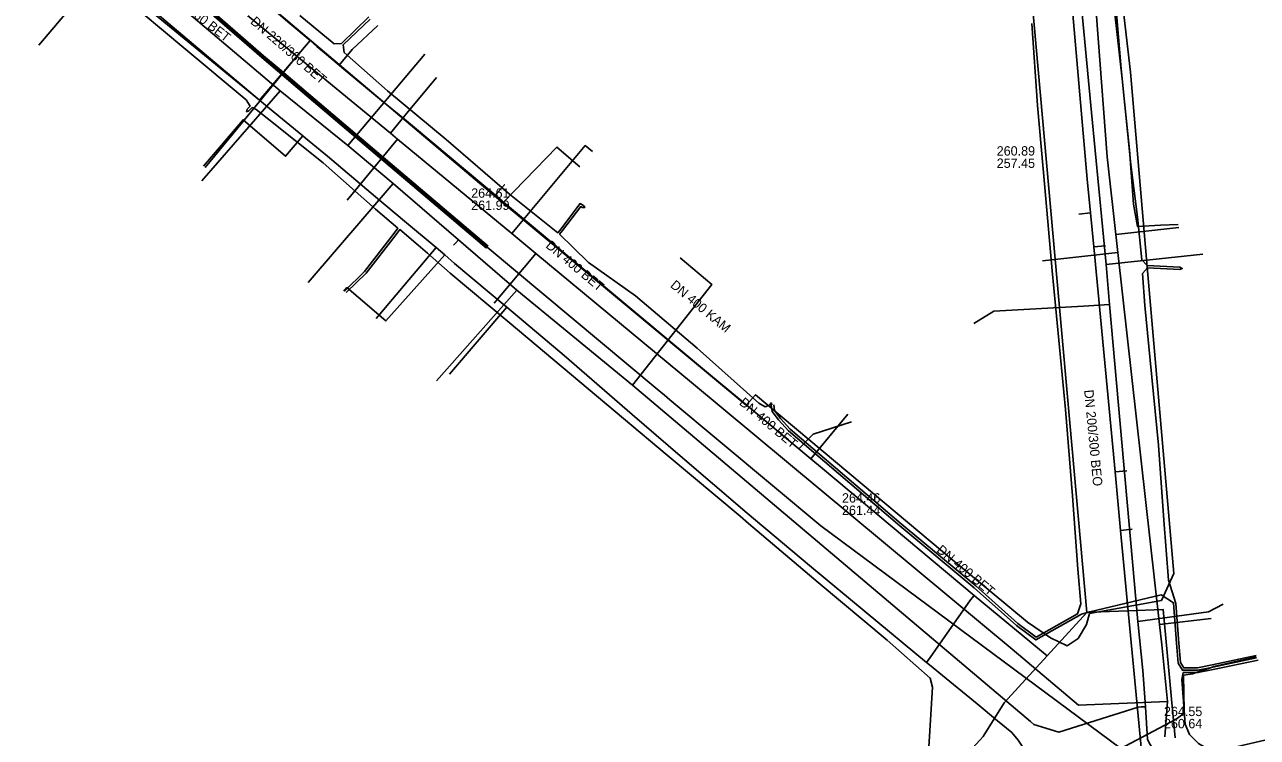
# Model space of a CAD drawing. Extents: x -600309 to -598967, y -1161267 to -1160292.
# Drawn here: x -599607.7 to -599502.5, y -1160506.1 to -1160445.2 of the extents above; entities that cross this region are included whole.
import ezdxf

# ---------------------------------------------------------------- set-up
doc = ezdxf.new("R2010")
doc.units = 0
for name, color, linetype in [('Vrstva 10', 7, 'Continuous'), ('Vrstva 12', 7, 'Continuous'), ('Vrstva 13', 7, 'Continuous'), ('Vrstva 16', 7, 'Continuous'), ('Vrstva 42', 7, 'Continuous'), ('Vrstva 55', 7, 'Continuous'), ('Vrstva 9', 7, 'Continuous')]:
    doc.layers.add(name, color=color, linetype=linetype)

msp = doc.modelspace()

# ---------------------------------------------------------------- linework, layer by layer
at = {"layer": 'Vrstva 10'}
for points in [[(-599568.27, -1160464.31), (-599572.94, -1160460.36), (-599578.12, -1160455.96), (-599583.58, -1160451.33), (-599586.1, -1160449.18), (-599587.42, -1160448.06), (-599594.65, -1160441.76)], [(-599594.51, -1160441.6), (-599587.28, -1160447.9), (-599585.96, -1160449.02), (-599583.44, -1160451.16), (-599577.98, -1160455.79), (-599572.79, -1160460.19), (-599568.13, -1160464.15)]]:
    msp.add_lwpolyline(points, dxfattribs=at)
at = {"layer": 'Vrstva 12'}
for points in [[(-599516.29, -1160425.96), (-599514.92, -1160442.02), (-599514.01, -1160450.14), (-599513.85, -1160451.58), (-599513.41, -1160455.92), (-599513.05, -1160460.58), (-599512.73, -1160462.46), (-599510.74, -1160462.37), (-599509.24, -1160462.29)], [(-599583.31, -1160446.61), (-599585.04, -1160445.15), (-599587.19, -1160443.33), (-599591.69, -1160439.53)], [(-599601.47, -1160440.31), (-599590.59, -1160449.26), (-599587.63, -1160451.7)], [(-599577.53, -1160445.33), (-599579.73, -1160447.38), (-599580.83, -1160448.71)], [(-599582.74, -1160447.1), (-599583.31, -1160446.61)], [(-599582.09, -1160447.64), (-599582.74, -1160447.1)], [(-599580.83, -1160448.71), (-599582.09, -1160447.64)], [(-599580.83, -1160448.71), (-599580.62, -1160448.89), (-599577.22, -1160451.71), (-599575.25, -1160453.32)], [(-599587.63, -1160451.7), (-599586.77, -1160452.41)], [(-599583.93, -1160454.74), (-599585.41, -1160456.48), (-599589.03, -1160453.36), (-599592.42, -1160457.31)], [(-599586.77, -1160452.41), (-599583.93, -1160454.74)], [(-599575.25, -1160453.32), (-599574.41, -1160454.03)], [(-599574.41, -1160454.03), (-599566.93, -1160460.28), (-599566.8, -1160460.39)], [(-599583.93, -1160454.74), (-599583.71, -1160454.93)], [(-599572.57, -1160464.27), (-599575.26, -1160462.01), (-599577.72, -1160459.94), (-599581.84, -1160456.47), (-599583.71, -1160454.93)], [(-599566.8, -1160460.39), (-599562.25, -1160455.69), (-599560.29, -1160457.39)], [(-599561.37, -1160464.94), (-599563.4, -1160463.24), (-599566.8, -1160460.39)], [(-599571.83, -1160464.9), (-599572.57, -1160464.27)], [(-599571.83, -1160464.9), (-599572.54, -1160465.68)], [(-599567.02, -1160468.95), (-599568.04, -1160468.1), (-599570.98, -1160465.62), (-599571.83, -1160464.9)], [(-599541.61, -1160481.46), (-599546.84, -1160477.08), (-599549.15, -1160475.15), (-599561.37, -1160464.94)], [(-599572.54, -1160465.68), (-599576.84, -1160470.53), (-599579.21, -1160468.51), (-599580.17, -1160467.69), (-599580.43, -1160468)], [(-599566.54, -1160469.35), (-599567.02, -1160468.95)], [(-599566.54, -1160469.35), (-599571.42, -1160475.08)], [(-599530.71, -1160499.68), (-599535.88, -1160495.42), (-599540.7, -1160491.4), (-599546.01, -1160486.93), (-599551.73, -1160482.05), (-599555.82, -1160478.52), (-599561.64, -1160473.48), (-599566.54, -1160469.35)], [(-599537.43, -1160478.49), (-599540.6, -1160482.3)], [(-599541.61, -1160481.46), (-599540.4, -1160480.2), (-599537.11, -1160479.14)], [(-599540.6, -1160482.3), (-599541.61, -1160481.46)], [(-599539.6, -1160483.13), (-599540.6, -1160482.3)], [(-599526.64, -1160493.97), (-599539.6, -1160483.13)], [(-599530.71, -1160499.68), (-599530.41, -1160499.25), (-599526.97, -1160494.35), (-599526.64, -1160493.97)], [(-599519.67, -1160514.71), (-599519.67, -1160514.49), (-599519.91, -1160512.92), (-599520.31, -1160511.39), (-599520.57, -1160510.64), (-599521.14, -1160509.36), (-599522.31, -1160507.22), (-599522.89, -1160506.32), (-599523.44, -1160505.66), (-599524.66, -1160504.67), (-599526.39, -1160503.22), (-599529.67, -1160500.53), (-599530.32, -1160500), (-599530.71, -1160499.68)]]:
    msp.add_lwpolyline(points, dxfattribs=at)
at = {"layer": 'Vrstva 13'}
for p, q in [((-599599.79, -1160439.1), (-599606.47, -1160447)), ((-599580.1, -1160455.56), (-599573.52, -1160447.77)), ((-599585.88, -1160450.88), (-599592.54, -1160458.58)), ((-599576.23, -1160458.79), (-599583.49, -1160467.26)), ((-599515.38, -1160465.73), (-599507.15, -1160464.84)), ((-599565.67, -1160467.9), (-599572.53, -1160475.66)), ((-599512.07, -1160503.06), (-599512.26, -1160500.36)), ((-599512.04, -1160503.46), (-599512.39, -1160503.48)), ((-599512.04, -1160503.46), (-599512.07, -1160503.06))]:
    msp.add_line(p, q, dxfattribs=at)
for points in [[(-599521.86, -1160504.71), (-599555.8, -1160476.01), (-599565.67, -1160467.9), (-599570.64, -1160463.61), (-599576.23, -1160458.79), (-599580.1, -1160455.56), (-599585.88, -1160450.88), (-599599.79, -1160439.1), (-599600.25, -1160438.69), (-599601.83, -1160437.36), (-599607.07, -1160433), (-599611.1, -1160429.81), (-599612.3, -1160428.8), (-599615.08, -1160426.38), (-599619.39, -1160422.7), (-599628.39, -1160414.76), (-599636.78, -1160407.58), (-599638.01, -1160406.45), (-599640.93, -1160403.96), (-599641.36, -1160403.58), (-599650.69, -1160395.73), (-599652.98, -1160393.88), (-599656.69, -1160390.81), (-599672.41, -1160377.69)], [(-599520.01, -1160415.26), (-599518.51, -1160432.89), (-599516.65, -1160452.74), (-599515.38, -1160465.73), (-599515.11, -1160469.13), (-599512.7, -1160496.18), (-599512.26, -1160500.36)], [(-599587.63, -1160451.7), (-599605.45, -1160436.64), (-599612.59, -1160430.72), (-599613.27, -1160431.54)], [(-599521.72, -1160443), (-599517.05, -1160495.41)], [(-599583.31, -1160446.61), (-599587.63, -1160451.7)], [(-599570.64, -1160463.61), (-599570.88, -1160463.87), (-599571.07, -1160464.07)], [(-599572.57, -1160464.27), (-599577.69, -1160470.33)], [(-599555.8, -1160476.01), (-599549.03, -1160467.43), (-599551.75, -1160465.16)], [(-599515.11, -1160469.13), (-599517.32, -1160469.26), (-599524.97, -1160469.7), (-599526.69, -1160470.76)], [(-599526.64, -1160493.97), (-599520.42, -1160499.12)], [(-599520.42, -1160499.12), (-599517.05, -1160495.41)], [(-599517.05, -1160495.41), (-599516.6, -1160495.39), (-599510.53, -1160495.16), (-599509.74, -1160503.73)], [(-599512.7, -1160496.18), (-599506.66, -1160495.37), (-599505.41, -1160494.7)], [(-599520.42, -1160499.12), (-599524.09, -1160503.13), (-599525.88, -1160506), (-599528.89, -1160509.29), (-599530.32, -1160521.07)], [(-599512.39, -1160503.48), (-599512.65, -1160503.5), (-599519.42, -1160505.64), (-599521.55, -1160504.99), (-599521.86, -1160504.71)], [(-599507.66, -1160514.21), (-599507.98, -1160513.58), (-599511.87, -1160506.25), (-599512.04, -1160503.46)], [(-599509.74, -1160503.73), (-599509.51, -1160506.11)]]:
    msp.add_lwpolyline(points, dxfattribs=at)
at = {"layer": 'Vrstva 16'}
for points in [[(-599518.29, -1160420.6), (-599517.52, -1160428.96), (-599516.84, -1160436.23), (-599515.3, -1160456.52), (-599514.56, -1160463.17), (-599514.39, -1160464.68), (-599510.84, -1160496.43), (-599510.65, -1160498.19), (-599510.17, -1160503.01), (-599510.38, -1160506.04)], [(-599598.06, -1160436.66), (-599584.45, -1160447.94), (-599576.46, -1160454.52), (-599575.86, -1160455.01), (-599566.09, -1160463.08), (-599564.06, -1160464.78), (-599550.76, -1160475.78), (-599523.41, -1160498.55), (-599517.74, -1160503.33), (-599510.17, -1160503.01)], [(-599584.45, -1160447.94), (-599592.27, -1160457.43)], [(-599572.54, -1160449.75), (-599575.19, -1160452.98), (-599576.46, -1160454.52)], [(-599575.86, -1160455.01), (-599580.15, -1160460.23)], [(-599566.09, -1160463.08), (-599559.83, -1160455.57), (-599559.21, -1160456.07)], [(-599514.56, -1160463.17), (-599509.18, -1160462.57)], [(-599567.6, -1160469.03), (-599567.46, -1160468.86), (-599564.6, -1160465.43), (-599564.06, -1160464.78)], [(-599514.39, -1160464.68), (-599519.77, -1160465.28)], [(-599519.77, -1160465.28), (-599520.81, -1160465.4)], [(-599510.84, -1160496.43), (-599506.44, -1160495.94)]]:
    msp.add_lwpolyline(points, dxfattribs=at)
at = {"layer": 'Vrstva 42'}
for points in [[(-599605.65, -1160437.46), (-599605.49, -1160437.66), (-599601.55, -1160440.96), (-599593.93, -1160447.37), (-599588.78, -1160451.66), (-599588.43, -1160452.2), (-599588.67, -1160452.47), (-599588.74, -1160452.68), (-599588.53, -1160452.6), (-599588.27, -1160452.33), (-599587.92, -1160452.48), (-599586.84, -1160453.34), (-599582.2, -1160457.03), (-599577.74, -1160460.99), (-599575.83, -1160462.62), (-599576.22, -1160463.16), (-599578.68, -1160466.32), (-599580.39, -1160467.98)], [(-599514.8, -1160440.89), (-599514.11, -1160449.03), (-599513.29, -1160457.18), (-599512.72, -1160461.68), (-599512.34, -1160465.32), (-599511.88, -1160465.81), (-599509.1, -1160465.94), (-599508.9, -1160466.05), (-599509.1, -1160466.14), (-599511.86, -1160466.01), (-599512.28, -1160466.49), (-599512.09, -1160469.21), (-599511.63, -1160473.89), (-599510.92, -1160481.13), (-599510.47, -1160487.53), (-599510.08, -1160492.65), (-599509.44, -1160494.65), (-599509.18, -1160498.03), (-599509.04, -1160499.68), (-599508.77, -1160500.15), (-599507.6, -1160500.14), (-599506.34, -1160499.88), (-599502.6, -1160499.1)], [(-599578.3, -1160444.59), (-599580.64, -1160446.85), (-599581.26, -1160446.89), (-599584.18, -1160444.46)], [(-599543.95, -1160477.5), (-599544.12, -1160477.71), (-599544.49, -1160477.87), (-599545.03, -1160477.55), (-599550.29, -1160472.87), (-599555.55, -1160468.39), (-599559.57, -1160465.54), (-599560.87, -1160464.27), (-599562.03, -1160463.13), (-599561.77, -1160462.81), (-599560.22, -1160460.78), (-599560.1, -1160460.85), (-599559.88, -1160460.86), (-599560, -1160460.67), (-599560.28, -1160460.52), (-599561.93, -1160462.69), (-599562.18, -1160463), (-599566.29, -1160459.7), (-599571.7, -1160455.06), (-599576.71, -1160450.89), (-599580.4, -1160447.61), (-599580.48, -1160446.96), (-599578.18, -1160444.77)], [(-599543.76, -1160477.69), (-599543.69, -1160478.19), (-599543.19, -1160478.86), (-599542.35, -1160479.77), (-599532.87, -1160487.85), (-599526.52, -1160493.14), (-599522.93, -1160496.37), (-599521.37, -1160497.52), (-599517.84, -1160495.54), (-599517.56, -1160494.68), (-599517.81, -1160491.72), (-599518.27, -1160485.45), (-599518.86, -1160478.1), (-599520, -1160466.25), (-599520.63, -1160459.14), (-599521.25, -1160452.14), (-599521.74, -1160445.15)], [(-599580.25, -1160468.12), (-599578.54, -1160466.46), (-599576.06, -1160463.28), (-599575.67, -1160462.74), (-599574.1, -1160464.06), (-599573.3, -1160464.75), (-599571.35, -1160466.45), (-599566.34, -1160470.66), (-599560.31, -1160475.74), (-599552.84, -1160481.98), (-599546.61, -1160487.21), (-599545.9, -1160487.81), (-599539.95, -1160492.85), (-599534.08, -1160497.77), (-599530.42, -1160501.02), (-599530.2, -1160501.78), (-599530.53, -1160506.91), (-599531.27, -1160514.43), (-599531.56, -1160515.17), (-599531.69, -1160515.36), (-599531.79, -1160515.36)], [(-599502.56, -1160499.3), (-599506.3, -1160500.08), (-599506.4, -1160500.1), (-599507.58, -1160500.34), (-599508.89, -1160500.35), (-599509.24, -1160499.74), (-599509.38, -1160498.05), (-599509.65, -1160494.59), (-599510.7, -1160493.92), (-599516.78, -1160495.37), (-599517.49, -1160495.57), (-599521.39, -1160497.76), (-599523.05, -1160496.53), (-599526.66, -1160493.3), (-599532.99, -1160488.01), (-599542.49, -1160479.91), (-599543.35, -1160478.98), (-599543.89, -1160478.27), (-599543.96, -1160477.72), (-599543.87, -1160477.6)], [(-599502.58, -1160499.2), (-599506.19, -1160500.03), (-599506.4, -1160500.1), (-599507.71, -1160500.54), (-599508, -1160500.64), (-599508.8, -1160500.76), (-599508.73, -1160503.79), (-599508.73, -1160504.01), (-599509.41, -1160504.53), (-599520.55, -1160510.42), (-599530.98, -1160515.64), (-599531.5, -1160516.2), (-599531.8, -1160520.72), (-599532.26, -1160521.55), (-599533.12, -1160522.25), (-599533.78, -1160522.57), (-599542.06, -1160528.06), (-599547.64, -1160531.75), (-599551.77, -1160534.64), (-599567.59, -1160545), (-599577.65, -1160550.79), (-599583.39, -1160553.94), (-599593.15, -1160558.79)], [(-599502.42, -1160499.48), (-599506.26, -1160500.28), (-599507.56, -1160500.54), (-599507.71, -1160500.54), (-599508.81, -1160500.55), (-599508.93, -1160501.15), (-599508.73, -1160503.79), (-599508.65, -1160504.94), (-599508.27, -1160505.84), (-599507.52, -1160506.59), (-599506.25, -1160507.35), (-599501.84, -1160506.32)]]:
    msp.add_lwpolyline(points, dxfattribs=at)
at = {"layer": 'Vrstva 55'}
for points in [[(-599510.04, -1160409.82), (-599511, -1160410.2), (-599512.29, -1160410.79), (-599510.29, -1160414.91), (-599511.82, -1160422.34), (-599516.77, -1160425.53), (-599515.88, -1160427.19), (-599513.31, -1160449.29), (-599511.94, -1160465.26), (-599509.63, -1160492.09)], [(-599588.87, -1160441.83), (-599567.58, -1160459.85), (-599566.73, -1160458.91), (-599567.58, -1160459.85), (-599546.1, -1160477.71), (-599545.3, -1160476.83), (-599536.2, -1160484.47), (-599528.46, -1160490.94), (-599522.09, -1160496.25), (-599520.13, -1160497.59), (-599518.73, -1160498.25), (-599517.79, -1160497.65), (-599517.08, -1160496.45), (-599516.81, -1160495.51), (-599510.68, -1160494.4), (-599509.63, -1160492.09)]]:
    msp.add_lwpolyline(points, dxfattribs=at)
at = {"layer": 'Vrstva 9'}
for p, q in [((-599517.72, -1160461.42), (-599516.73, -1160461.32)), ((-599568.2, -1160464.23), (-599553.7, -1160476.36)), ((-599515.46, -1160464.12), (-599516.45, -1160464.22)), ((-599552.62, -1160477.26), (-599539.75, -1160488.03)), ((-599513.63, -1160483.33), (-599514.63, -1160483.42)), ((-599539.75, -1160488.03), (-599512.26, -1160508.42)), ((-599513.16, -1160488.32), (-599514.16, -1160488.41))]:
    msp.add_line(p, q, dxfattribs=at)
for points in [[(-599517, -1160458.43), (-599519.64, -1160428.29), (-599520.55, -1160416.56), (-599520.64, -1160414.9), (-599520.44, -1160413.23), (-599520.19, -1160412), (-599519.76, -1160411.06), (-599519.26, -1160410.13), (-599518.76, -1160409.4), (-599518.12, -1160408.66), (-599517.64, -1160408.24)], [(-599594.58, -1160441.68), (-599587.35, -1160447.98), (-599586.03, -1160449.1), (-599583.51, -1160451.24), (-599578.05, -1160455.87), (-599572.86, -1160460.27), (-599568.2, -1160464.23)], [(-599512.26, -1160508.42), (-599514.16, -1160488.41), (-599514.63, -1160483.42), (-599516.45, -1160464.22), (-599516.73, -1160461.32), (-599517, -1160458.43)], [(-599553.7, -1160476.36), (-599553.08, -1160476.88), (-599552.62, -1160477.26)]]:
    msp.add_lwpolyline(points, dxfattribs=at)

# ---------------------------------------------------------------- texts
at = {"layer": 'Vrstva 12'}
for s, rotation, p in [('DN 220/360 BET', 322.1262, (-599596.88, -1160441.81)), ('DN 220/360 BET', 319.1184, (-599588.47, -1160445.08)), ('DN 400 BET', 320.0857, (-599563.27, -1160464.21)), ('DN 400 KAM', 320.0857, (-599552.64, -1160467.59)), ('DN 200/300 BEO', 275.4208, (-599517.27, -1160476.44)), ('DN 400 BET', 320.0856, (-599546.76, -1160477.61)), ('DN 400 BET', 319.9969, (-599529.92, -1160490.19))]:
    msp.add_text(s, height=0.8, rotation=rotation, dxfattribs=at).set_placement(p)
for s, p in [('260.89', (-599524.73, -1160456.42)), ('257.45', (-599524.73, -1160457.47)), ('264.61', (-599569.57, -1160460.02)), ('261.99', (-599569.57, -1160461.06)), ('264.46', (-599537.93, -1160486.04)), ('261.44', (-599537.93, -1160487.09)), ('264.55', (-599510.46, -1160504.26)), ('260.64', (-599510.46, -1160505.3))]:
    msp.add_text(s, height=0.8, dxfattribs=at).set_placement(p)

doc.saveas('drawing.dxf')
